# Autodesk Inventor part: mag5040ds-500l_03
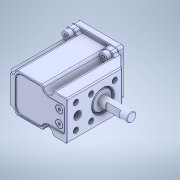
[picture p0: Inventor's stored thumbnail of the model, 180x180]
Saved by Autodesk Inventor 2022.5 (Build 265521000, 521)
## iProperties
Created: 2023-04
Part Number: mag5040ds-500l_03
Material: Generic
Document SubType Name: Modeling
Designer: ImaoCorp
Density: 1 g/cm^3
Appearance: Default
Author: ImaoCorp
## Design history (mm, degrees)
feature "mag5040ds-500l_03"
node "ソリッド1"
